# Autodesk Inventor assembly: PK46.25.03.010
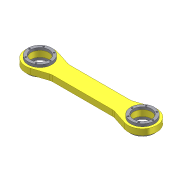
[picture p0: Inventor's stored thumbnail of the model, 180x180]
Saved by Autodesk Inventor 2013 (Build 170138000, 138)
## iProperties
Created: 2005-04
Part Number: PK46.25.03.010
Document SubType Name: Assembly
Designer: salex
Manufacturer: Standard
Standards Organization: Custom
Description: Тяга
Author: salex
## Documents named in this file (3)
- C:\Product Design Suite 2013 Test Drive\Dynamic Simulation\Workspace\Assy, Chassis, Front\PK46.25.03.010.iam
- C:\Product Design Suite 2013 Test Drive\Dynamic Simulation\Workspace\Assy, Chassis, Front\PK46.25.03.001.ipt
- C:\Product Design Suite 2013 Test Drive\Dynamic Simulation\Workspace\Assy, Chassis, Front\PK46.25.01.004.ipt
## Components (5 placed, 2 different names)
1. PK46.25.03.001:1 — Вставка:1, Вставка:2, Вставка:3, Вставка:4
2. PK46.25.01.004:1 — Вставка:1
3. PK46.25.01.004:2 — Вставка:3
4. PK46.25.01.004:3 — Вставка:2
5. PK46.25.01.004:4 — Вставка:4
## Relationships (4: Insert 4)
- Вставка:1 [Insert]: PK46.25.03.001:1 ↔ PK46.25.01.004:1
- Вставка:2 [Insert]: PK46.25.03.001:1 ↔ PK46.25.01.004:3
- Вставка:3 [Insert]: PK46.25.03.001:1 ↔ PK46.25.01.004:2
- Вставка:4 [Insert]: PK46.25.03.001:1 ↔ PK46.25.01.004:4
